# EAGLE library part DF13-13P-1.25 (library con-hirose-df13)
DF13-13P 1.25mm Pitch Miniature Crimping Connector.
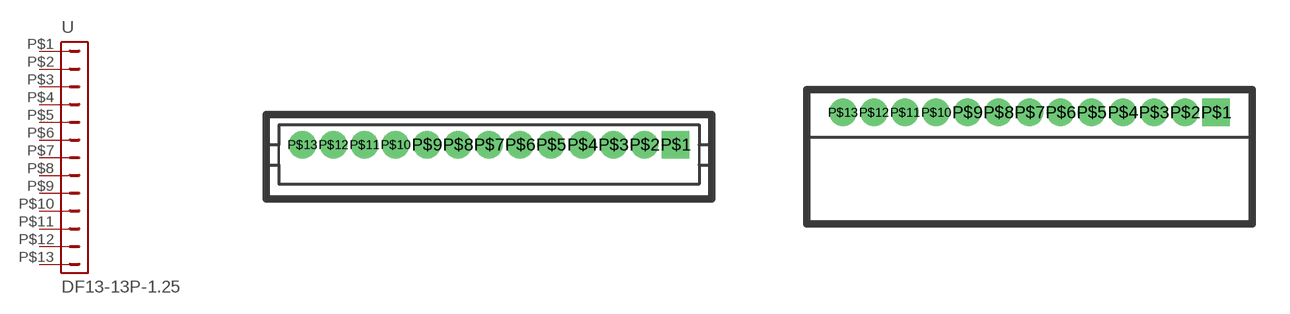
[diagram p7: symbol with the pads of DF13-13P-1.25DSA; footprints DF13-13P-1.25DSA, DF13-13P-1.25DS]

Designator prefix -

## DF13-13P-1.25DSA  [DF13-13P-1.25DSA]
P$1  1  pas
P$2  2  pas
P$3  3  pas
P$4  4  pas
P$5  5  pas
P$6  6  pas
P$7  7  pas
P$8  8  pas
P$9  9  pas
P$10  10  pas
P$11  11  pas
P$12  12  pas
P$13  13  pas

## DF13-13P-1.25DS  [DF13-13P-1.25DS]
Pads as for DF13-13P-1.25DSA

## Footprint DF13-13P-1.25DSA (pad centres in mm)
Single Row Straight Pin Header (Through hole)
drill 0.6 pad 1.016 square: P$1 7.5,0
drill 0.6 pad 1.016 round: P$2 6.25,0; P$3 5,0; P$4 3.75,0; P$5 2.5,0; P$6 1.25,0; P$7 0,0; P$8 -1.25,0; P$9 -2.5,0; P$10 -3.75,0; P$11 -5,0; P$12 -6.25,0; P$13 -7.5,0

## Footprint DF13-13P-1.25DS (pad centres in mm)
Single Row Right Angle Pin Header (Through hole)
drill 0.6 pad 1.016 square: P$1 7.5,0
drill 0.6 pad 1.016 round: P$2 6.25,0; P$3 5,0; P$4 3.75,0; P$5 2.5,0; P$6 1.25,0; P$7 0,0; P$8 -1.25,0; P$9 -2.5,0; P$10 -3.75,0; P$11 -5,0; P$12 -6.25,0; P$13 -7.5,0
